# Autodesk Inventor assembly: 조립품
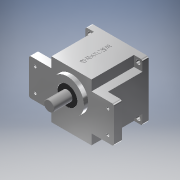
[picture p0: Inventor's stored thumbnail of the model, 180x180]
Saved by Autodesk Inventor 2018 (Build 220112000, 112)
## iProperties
Created: 2020-07
Part Number: 조립품
Material: 일반
Document SubType Name: Assembly
Designer: admin
Author: admin
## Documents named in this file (10)
- C:\Users\admin\Desktop\700707V1003\조립품.iam
- C:\Users\admin\Desktop\700707V1003\본체.ipt
- C:\Users\admin\Desktop\700707V1003\커버.ipt
- C:\Users\admin\Desktop\700707V1003\메인 축.ipt
- C:\Users\admin\Desktop\700707V1003\서브 축.ipt
- C:\Users\admin\Desktop\700707V1003\볼트 M4.ipt
- C:\Users\admin\Desktop\700707V1003\베어링 6003.ipt
- C:\Users\admin\Desktop\700707V1003\베어링 608.ipt
- C:\Users\admin\Desktop\700707V1003\오일 실 17 32 8.ipt
- C:\Users\admin\Desktop\700707V1003\오일 실 8 22 7.ipt
